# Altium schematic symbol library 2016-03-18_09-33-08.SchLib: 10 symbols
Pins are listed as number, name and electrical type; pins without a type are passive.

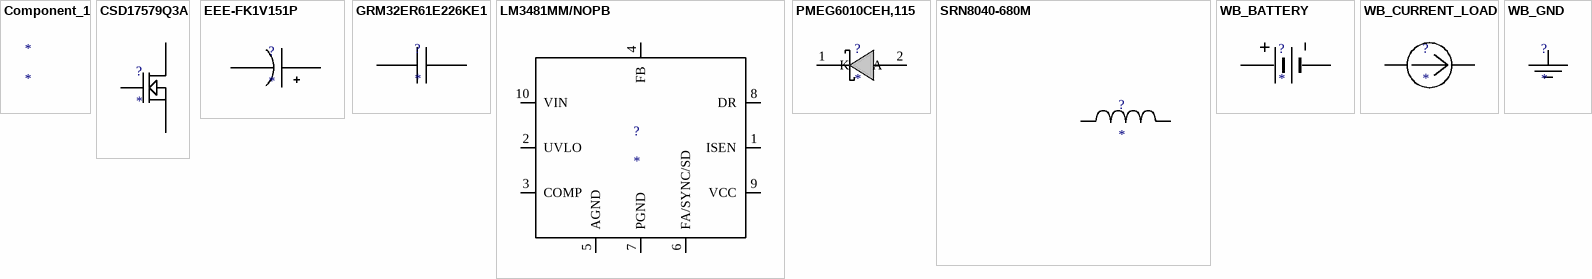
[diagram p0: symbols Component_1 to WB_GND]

## Component_1
designator *

## CSD17579Q3A
designator ?
Imported; Manufacturer_Part_Number: CSD17579Q3A; VdsMax: 30.0V; IdsMax: 11.0A; Rdsonat10V: 0.0087Ohm; QgTyp: 5.3nC; Vendor: Texas Instruments
footprint TRANS_NexFET_Q3A
pins: 1 Source, 2 Source, 3 Source, 4 Gate, 5 Drain, 6 Drain, 7 Drain, 8 Drain, 9 Drain

## EEE-FK1V151P
designator ?
Imported; Manufacturer_Part_Number: EEE-FK1V151P; Vendor: Panasonic
footprint SM_RADIAL_F
pins: 1 +, 2 -

## GRM32ER61E226KE1
designator ?
Imported; Manufacturer_Part_Number: GRM32ER61E226KE15L; Vendor: MuRata
footprint 1210
pins: 1, 2

## LM3481MM/NOPB
designator ?
Imported; Frequency: 1000000.0; Imax: 20.0; Mktg_Package: NA; NSID: LM3481MM/NOPB; Vendor: Texas Instruments
footprint MUB10A
pins: 1 ISEN, 2 UVLO, 3 COMP, 4 FB, 5 AGND, 6 FA/SYNC/SD, 7 PGND, 8 DR, 9 VCC, 10 VIN

## PMEG6010CEH,115
designator ?
Imported; Manufacturer_Part_Number: PMEG6010CEH,115; Vendor: NXP Semiconductor
footprint SOD-123F
pins: 1 K, 2 A

## SRN8040-680M
designator ?
Imported; Manufacturer_Part_Number: SRN8040-680M; Vendor: Bourns
footprint SRN8040
pins: 1, 2

## WB_BATTERY
designator ?
Imported; Manufacturer_Part_Number: WB_BATTERY; PowerPortType: POWER_GROUND
pins: 1 +, 2 -

## WB_CURRENT_LOAD
designator ?
Imported; Manufacturer_Part_Number: WB_CURRENT_LOAD; PowerPortType: POWER_GROUND
pins: 1 +, 2 -

## WB_GND
designator ?
Imported; Manufacturer_Part_Number: WB_GND; PowerPortType: POWER_GROUND
pins: 1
